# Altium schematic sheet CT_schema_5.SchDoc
size 287 x 160 mm
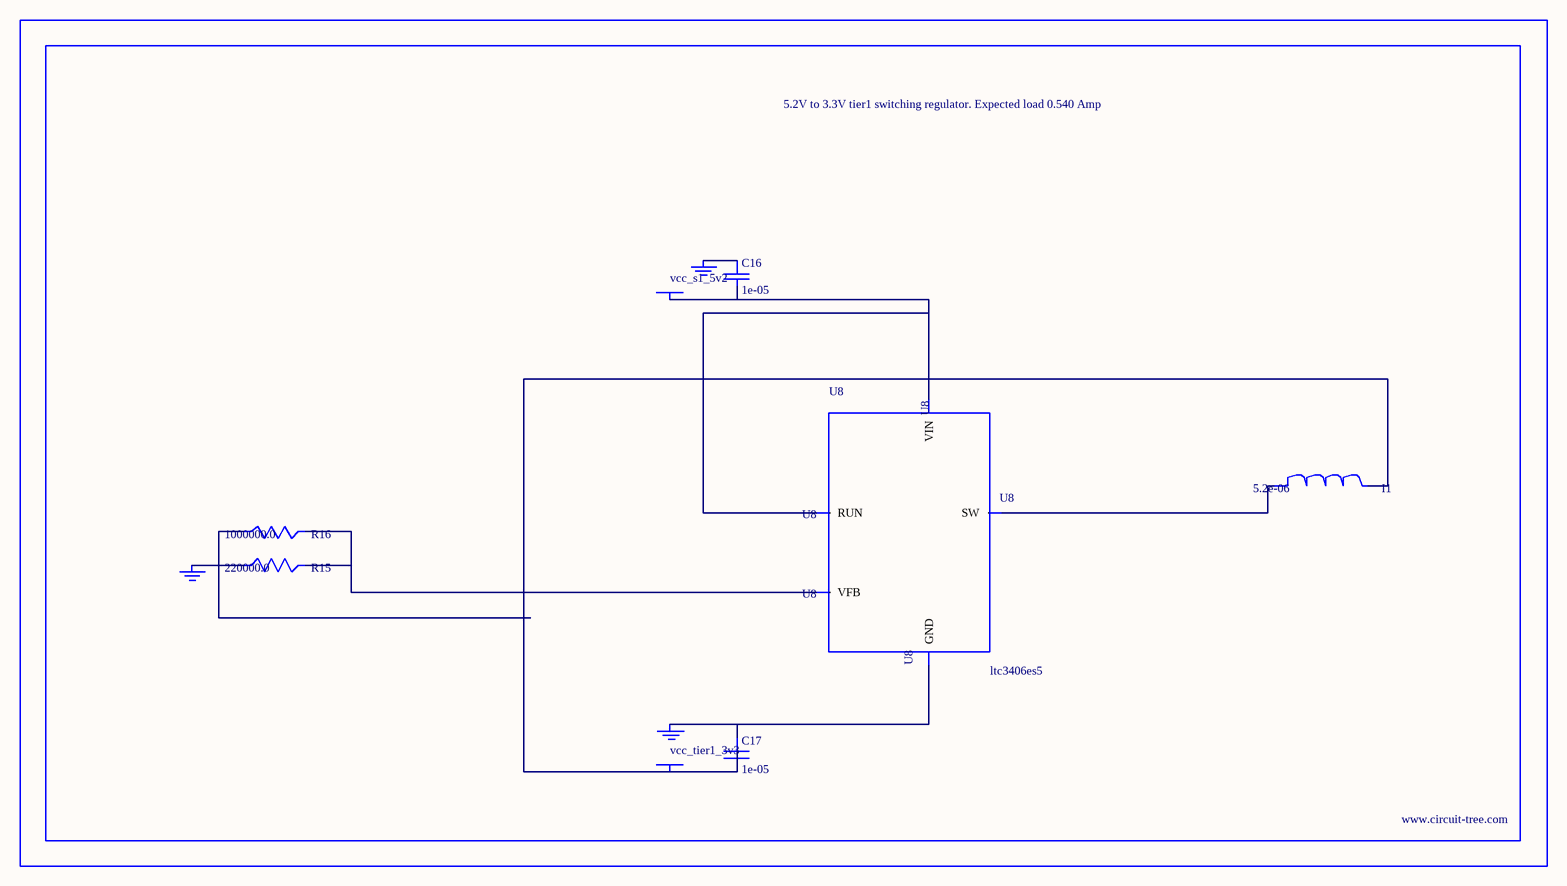
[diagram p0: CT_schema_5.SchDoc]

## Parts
BORDER4  (no value)
C16  1e-05  [C0805]
C17  1e-05  [C0805]
GND_INSTANCE_4_0  (no value)
GND_INSTANCE_4_1  (no value)
GND_INSTANCE_4_2  (no value)
I1  5.2e-06  [DR1040]
POWER_INSTANCE_4_0  vcc_tier1_3v3
POWER_INSTANCE_4_1  vcc_s1_5v2
R15  220000.0  [R0603]
R16  1000000.0  [R0603]
U8  ltc3406es5  [TSOT-23-5]

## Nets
NetC16_1: C16.1 GND_INSTANCE_4_1.0(GND)
NetC16_2: C16.2 POWER_INSTANCE_4_1.0(PWR) U8.1(RUN) U8.4(VIN)
NetC17_1: C17.1 GND_INSTANCE_4_0.0(GND) U8.2(GND)
NetC17_2: C17.2 I1.2 POWER_INSTANCE_4_0.0(PWR) R16.1
NetGND_INSTANCE_4_2_0: GND_INSTANCE_4_2.0(GND) R15.1
NetI1_1: I1.1 U8.3(SW)
NetR15_2: R15.2 R16.2 U8.5(VFB)

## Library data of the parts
BORDER4 = BORDER_PAGE4
C16 C17 = C0805C106K8RACTU
GND_INSTANCE_4_0-GND_INSTANCE_4_2 = GND
I1 = DR1040-5R2-R
POWER_INSTANCE_4_0 POWER_INSTANCE_4_1 = PWR
R15 = RC0603JR-07220KL
R16 = RC0603JR-071ML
